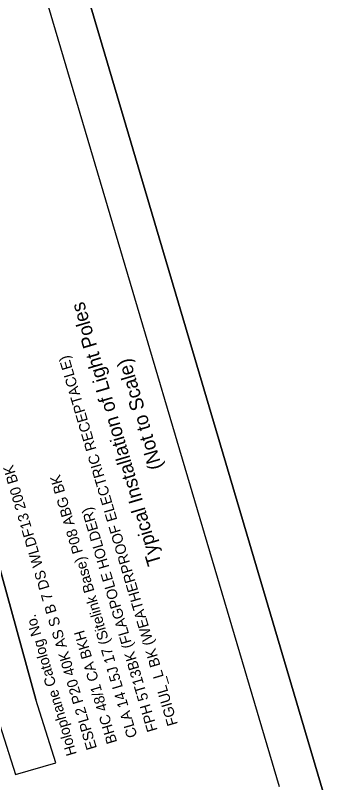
# Model space of a CAD drawing. Extents: x 1111051 to 1111820, y 617600 to 618625.
# Drawn here: x 1111693.5 to 1111819.8, y 617845.8 to 618136.5 of the extents above; entities that cross this region are included whole.
import ezdxf

# ---------------------------------------------------------------- set-up
doc = ezdxf.new("R2010")
doc.units = 0
for name, color, linetype in [('BORDER', 7, 'Continuous'), ('D_Roadway_SubGrade', 7, 'Continuous'), ('Default', 7, 'Continuous'), ('PATTERNING', 7, 'Continuous'), ('PLOT BOUNDARY', 7, 'Continuous'), ('Prp Liting', 7, 'Continuous')]:
    doc.layers.add(name, color=color, linetype=linetype)

msp = doc.modelspace()

# ---------------------------------------------------------------- linework, layer by layer
at = {"layer": 'BORDER'}
msp.add_line((1111793.62, 617844.23), (1111566.53, 618611.32), dxfattribs=at)
at = {"layer": 'D_Roadway_SubGrade'}
for p in [(1111677.94, 617962.03), (1111708.8, 617853.38)]:
    msp.add_line(p, (1111701.19, 617877.3), dxfattribs=at)
at = {"layer": 'Default'}
msp.add_lwpolyline([(1111292.39, 617653.65), (1111051.12, 618468.69), (1111578.49, 618624.81), (1111819.77, 617809.77)], close=True, dxfattribs=at)
at = {"layer": 'PATTERNING'}
for p, q in [((1111701.19, 617877.3), (1111677.94, 617962.03)), ((1111708.8, 617853.38), (1111701.19, 617877.3)), ((1111685.88, 617872.77), (1111693.48, 617848.85)), ((1111693.48, 617848.85), (1111708.8, 617853.38))]:
    msp.add_line(p, q, dxfattribs=at)
at = {"layer": 'PLOT BOUNDARY'}
msp.add_lwpolyline([(1111819.77, 617809.77), (1111578.49, 618624.81), (1111051.12, 618468.69), (1111292.39, 617653.65)], close=True, dxfattribs=at)

# ---------------------------------------------------------------- texts
at = {"layer": 'Prp Liting'}
for s, height, p in [('Typical Installation of Light Poles', 5.324, (1111748.85, 617928.92)), ('FGIUL_L BK (WEATHERPROOF ELECTRIC RECEPTACLE)', 3.993, (1111755.07, 617868)), ('(Not to Scale)', 5.324, (1111749.21, 617965.21)), ('ESPL2 P20 40K AS S B 7 DS WLDF13 200 BK', 3.993, (1111724.43, 617858.93)), ('CLA 14 L5J 17 (Sitelink Base) P08 ABG BK', 3.993, (1111739.75, 617863.47)), ('FPH 5T13BK (FLAGPOLE HOLDER)', 3.993, (1111747.41, 617865.73)), ('Holophane Catolog No.', 3.993, (1111716.78, 617856.67)), ('BHC 48/1 CA BKH', 3.993, (1111732.09, 617861.2))]:
    msp.add_text(s, height=height, rotation=106.4903, dxfattribs=at).set_placement(p)

doc.saveas('drawing.dxf')
